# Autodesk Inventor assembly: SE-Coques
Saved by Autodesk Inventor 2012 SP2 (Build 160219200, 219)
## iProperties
Created: 2013-08
Part Number: SE-Coques
Document SubType Name: Assembly
Designer: hilarion
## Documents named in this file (5)
- L:\STI2D\Ressources eleves\ITEC\Tsti2d Fichot 2013-14\Webcam motorisee\SE-Coques.iam
- L:\STI2D\Ressources eleves\ITEC\Tsti2d Fichot 2013-14\Webcam motorisee\Coque avant.ipt
- L:\STI2D\Ressources eleves\ITEC\Tsti2d Fichot 2013-14\Webcam motorisee\Coque arriere.ipt
- L:\STI2D\Ressources eleves\ITEC\Tsti2d Fichot 2013-14\Webcam motorisee\ensemble_mobile axe y.iam
- L:\STI2D\Ressources eleves\ITEC\Tsti2d Fichot 2013-14\Webcam motorisee\Roue dentée Intermédiaire 12.ipt
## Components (4 placed, 4 different names)
1. Coque avant:1
2. Coque arriere:1
3. ensemble_mobile axe y:1 [sub-assembly]
4. Roue dentée Intermédiaire 12:1
